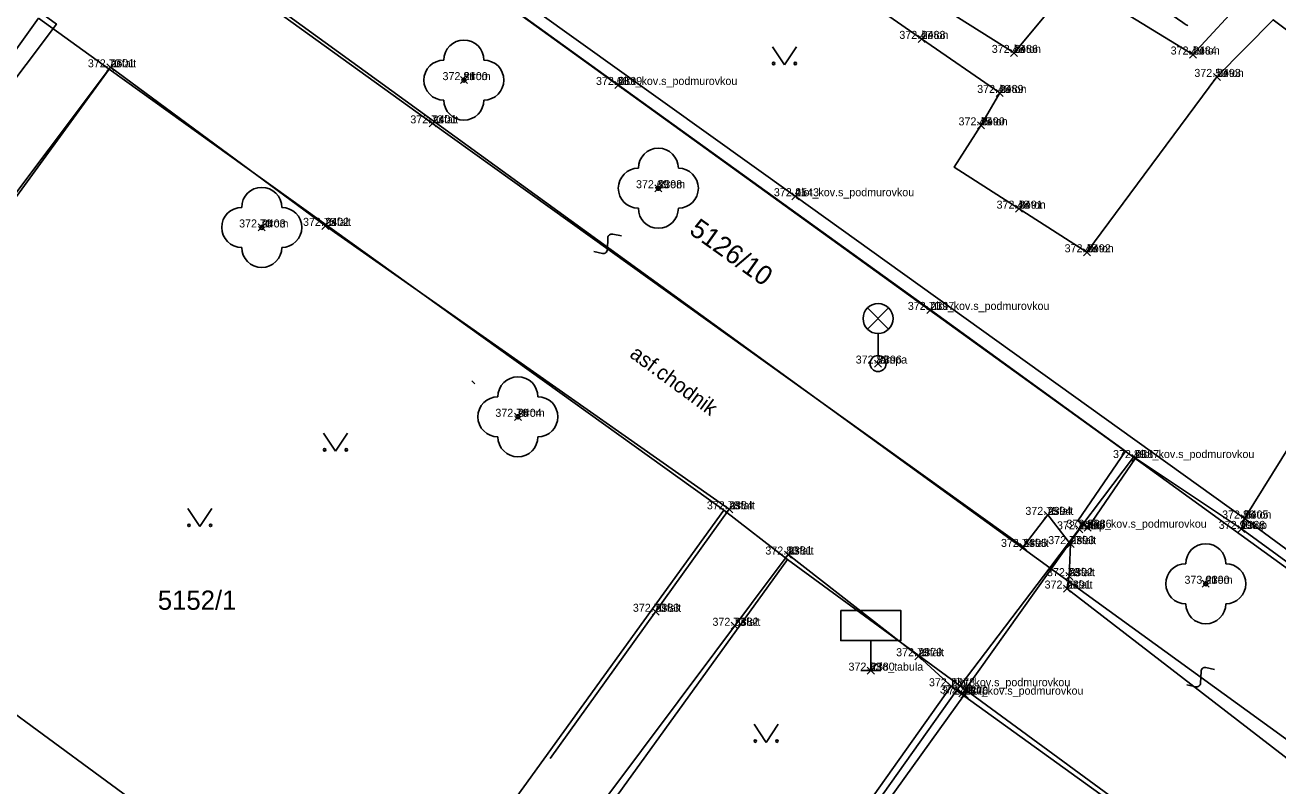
# Model space of a CAD drawing. Extents: x -400488 to -400124, y -1251493 to -1251223.
# Drawn here: x -400364.05 to -400332.74, y -1251372.84 to -1251353.83 of the extents above; entities that cross this region are included whole.
import ezdxf

# ---------------------------------------------------------------- set-up
doc = ezdxf.new("R2010")
doc.units = 0
for name, color, linetype in [('Level 20', 7, 'Continuous'), ('Level 21', 7, 'Continuous'), ('Level 22', 7, 'Continuous'), ('Level 23', 7, 'Continuous'), ('Level 31', 7, 'Continuous'), ('Level 32', 7, 'Continuous'), ('Level 35', 7, 'Continuous'), ('Level 36', 7, 'Continuous'), ('Level 49', 7, 'Continuous'), ('Level 53', 7, 'Continuous'), ('Level 63', 7, 'Continuous')]:
    doc.layers.add(name, color=color, linetype=linetype)

msp = doc.modelspace()

# ---------------------------------------------------------------- linework, layer by layer
at = {"layer": 'Level 20'}
for p, q in [((-400341.728, -1251354.268), (-400341.552, -1251354.092)), ((-400341.552, -1251354.268), (-400341.728, -1251354.092)), ((-400339.418, -1251354.618), (-400339.242, -1251354.442)), ((-400339.242, -1251354.618), (-400339.418, -1251354.442)), ((-400334.948, -1251354.658), (-400334.772, -1251354.482)), ((-400334.772, -1251354.658), (-400334.948, -1251354.482)), ((-400361.998, -1251354.978), (-400361.822, -1251354.802)), ((-400361.822, -1251354.978), (-400361.998, -1251354.802)), ((-400353.168, -1251355.298), (-400352.992, -1251355.122)), ((-400352.992, -1251355.298), (-400353.168, -1251355.122)), ((-400334.348, -1251355.218), (-400334.172, -1251355.042)), ((-400334.172, -1251355.218), (-400334.348, -1251355.042)), ((-400349.308, -1251355.418), (-400349.132, -1251355.242)), ((-400349.132, -1251355.418), (-400349.308, -1251355.242)), ((-400339.778, -1251355.618), (-400339.602, -1251355.442)), ((-400339.602, -1251355.618), (-400339.778, -1251355.442)), ((-400353.948, -1251356.378), (-400353.772, -1251356.202)), ((-400353.772, -1251356.378), (-400353.948, -1251356.202)), ((-400340.248, -1251356.428), (-400340.072, -1251356.252)), ((-400340.072, -1251356.428), (-400340.248, -1251356.252)), ((-400348.308, -1251357.998), (-400348.132, -1251357.822)), ((-400348.132, -1251357.998), (-400348.308, -1251357.822)), ((-400344.888, -1251358.198), (-400344.712, -1251358.022)), ((-400344.712, -1251358.198), (-400344.888, -1251358.022)), ((-400339.298, -1251358.508), (-400339.122, -1251358.332)), ((-400339.122, -1251358.508), (-400339.298, -1251358.332)), ((-400358.218, -1251358.978), (-400358.042, -1251358.802)), ((-400358.042, -1251358.978), (-400358.218, -1251358.802)), ((-400356.628, -1251358.938), (-400356.452, -1251358.762)), ((-400356.452, -1251358.938), (-400356.628, -1251358.762)), ((-400337.598, -1251359.598), (-400337.422, -1251359.422)), ((-400337.422, -1251359.598), (-400337.598, -1251359.422)), ((-400341.508, -1251361.038), (-400341.332, -1251360.862)), ((-400341.332, -1251361.038), (-400341.508, -1251360.862)), ((-400342.818, -1251362.378), (-400342.642, -1251362.202)), ((-400342.642, -1251362.378), (-400342.818, -1251362.202)), ((-400351.818, -1251363.708), (-400351.642, -1251363.532)), ((-400351.642, -1251363.708), (-400351.818, -1251363.532)), ((-400336.388, -1251364.738), (-400336.212, -1251364.562)), ((-400336.212, -1251364.738), (-400336.388, -1251364.562)), ((-400346.538, -1251366.018), (-400346.362, -1251365.842)), ((-400346.362, -1251366.018), (-400346.538, -1251365.842)), ((-400338.578, -1251366.158), (-400338.402, -1251365.982)), ((-400338.402, -1251366.158), (-400338.578, -1251365.982)), ((-400333.658, -1251366.248), (-400333.482, -1251366.072)), ((-400333.482, -1251366.248), (-400333.658, -1251366.072)), ((-400337.788, -1251366.518), (-400337.612, -1251366.342)), ((-400337.612, -1251366.518), (-400337.788, -1251366.342)), ((-400337.578, -1251366.478), (-400337.402, -1251366.302)), ((-400337.402, -1251366.478), (-400337.578, -1251366.302)), ((-400333.738, -1251366.508), (-400333.562, -1251366.332)), ((-400333.562, -1251366.508), (-400333.738, -1251366.332)), ((-400339.188, -1251366.958), (-400339.012, -1251366.782)), ((-400339.012, -1251366.958), (-400339.188, -1251366.782)), ((-400338.008, -1251366.888), (-400337.832, -1251366.712)), ((-400337.832, -1251366.888), (-400338.008, -1251366.712)), ((-400345.068, -1251367.148), (-400344.892, -1251366.972)), ((-400344.892, -1251367.148), (-400345.068, -1251366.972)), ((-400338.038, -1251367.688), (-400337.862, -1251367.512)), ((-400337.862, -1251367.688), (-400338.038, -1251367.512)), ((-400334.628, -1251367.878), (-400334.452, -1251367.702)), ((-400334.452, -1251367.878), (-400334.628, -1251367.702)), ((-400338.098, -1251367.998), (-400337.922, -1251367.822)), ((-400337.922, -1251367.998), (-400338.098, -1251367.822)), ((-400348.378, -1251368.578), (-400348.202, -1251368.402)), ((-400348.202, -1251368.578), (-400348.378, -1251368.402)), ((-400346.398, -1251368.928), (-400346.222, -1251368.752)), ((-400346.222, -1251368.928), (-400346.398, -1251368.752)), ((-400341.808, -1251369.688), (-400341.632, -1251369.512)), ((-400341.632, -1251369.688), (-400341.808, -1251369.512)), ((-400342.998, -1251370.048), (-400342.822, -1251369.872)), ((-400342.822, -1251370.048), (-400342.998, -1251369.872)), ((-400340.988, -1251370.438), (-400340.812, -1251370.262)), ((-400340.812, -1251370.438), (-400340.988, -1251370.262)), ((-400340.708, -1251370.618), (-400340.532, -1251370.442)), ((-400340.532, -1251370.618), (-400340.708, -1251370.442)), ((-400340.658, -1251370.648), (-400340.482, -1251370.472)), ((-400340.482, -1251370.648), (-400340.658, -1251370.472))]:
    msp.add_line(p, q, dxfattribs=at)
at = {"layer": 'Level 31'}
for points in [[(-400325.3, -1251345.13), (-400328.44, -1251348.18), (-400333.54, -1251353.13), (-400334.86, -1251354.57), (-400337.85, -1251352.74), (-400339.33, -1251354.53), (-400341.3, -1251353.29)], [(-400341.64, -1251354.18), (-400348.59, -1251349.35), (-400349.96, -1251351.43), (-400354.01, -1251348.56)], [(-400340.16, -1251356.34), (-400340.828, -1251357.382), (-400337.51, -1251359.51), (-400334.26, -1251355.13), (-400332.86, -1251353.7), (-400328.72, -1251356.82), (-400328.3, -1251357.14), (-400327.46, -1251357.74), (-400326.93, -1251358.11), (-400329.7, -1251364.82)], [(-400341.64, -1251354.18), (-400339.69, -1251355.53), (-400340.16, -1251356.34)], [(-400333.57, -1251366.16), (-400331.94, -1251363.54), (-400331.46, -1251363.76), (-400331.01, -1251364.01), (-400330.04, -1251364.51), (-400329.7, -1251364.82), (-400328.94, -1251365.47), (-400330.88, -1251368.13), (-400333.57, -1251366.16)]]:
    msp.add_lwpolyline(points, dxfattribs=at)
at = {"layer": 'Level 32'}
for p, q in [((-400342.91, -1251369.96), (-400342.91, -1251369.21)), ((-400343.16, -1251369.96), (-400342.66, -1251369.96))]:
    msp.add_line(p, q, dxfattribs=at)
for points in [[(-400385.43, -1251329.24), (-400385.81, -1251330.02), (-400386.13, -1251330.85), (-400386.185, -1251331.545), (-400386.09, -1251332.46), (-400385.712, -1251333.158), (-400385.21, -1251333.75), (-400379.16, -1251338.08), (-400353.86, -1251356.29)], [(-400365.68, -1251352.04), (-400363.26, -1251353.81), (-400367.84, -1251359.89)], [(-400361.91, -1251354.89), (-400366.49, -1251360.97)], [(-400350.926, -1251372.157), (-400346.45, -1251365.93), (-400356.54, -1251358.85), (-400361.91, -1251354.89)], [(-400332, -1251372.55), (-400338.01, -1251367.91), (-400337.95, -1251367.6), (-400337.92, -1251366.8), (-400338.49, -1251366.07), (-400339.1, -1251366.87), (-400353.86, -1251356.29)], [(-400340.9, -1251370.35), (-400341.72, -1251369.6), (-400344.98, -1251367.06), (-400349.554, -1251373.182)]]:
    msp.add_lwpolyline(points, dxfattribs=at)
msp.add_lwpolyline([(-400343.66, -1251368.46), (-400342.16, -1251368.46), (-400342.16, -1251369.21), (-400343.66, -1251369.21)], close=True, dxfattribs=at)
at = {"layer": 'Level 35'}
msp.add_line((-400345.145, -1251376.318), (-400340.9, -1251370.35), dxfattribs=at)
for points in [[(-400336.543, -1251364.474), (-400341.42, -1251360.95), (-400349.22, -1251355.33), (-400374.14, -1251337.36)], [(-400333.65, -1251366.42), (-400333.57, -1251366.16), (-400344.8, -1251358.11), (-400358.88, -1251348.03)], [(-400337.49, -1251366.39), (-400337.738, -1251366.221), (-400336.543, -1251364.474)], [(-400337.49, -1251366.39), (-400336.3, -1251364.65), (-400333.65, -1251366.42)], [(-400340.62, -1251370.53), (-400337.7, -1251366.43), (-400337.614, -1251366.305)], [(-400333.65, -1251366.42), (-400329.68, -1251369.31)], [(-400344.859, -1251376.524), (-400340.57, -1251370.56), (-400340.62, -1251370.53), (-400340.9, -1251370.35)]]:
    msp.add_lwpolyline(points, dxfattribs=at)
at = {"layer": 'Level 36'}
for p, q in [((-400345.07, -1251354.825), (-400345.37, -1251354.375)), ((-400345.07, -1251354.825), (-400344.77, -1251354.375)), ((-400356.289, -1251364.475), (-400356.589, -1251364.025)), ((-400356.289, -1251364.475), (-400355.989, -1251364.025)), ((-400345.527, -1251371.751), (-400345.827, -1251371.301)), ((-400345.527, -1251371.751), (-400345.227, -1251371.301))]:
    msp.add_line(p, q, dxfattribs=at)
for centre, radius in [((-400345.34, -1251354.795), 0.03), ((-400344.8, -1251354.795), 0.03), ((-400353.08, -1251355.21), 0.05), ((-400348.22, -1251357.91), 0.05), ((-400358.13, -1251358.89), 0.05), ((-400351.73, -1251363.62), 0.05), ((-400356.559, -1251364.445), 0.03), ((-400356.019, -1251364.445), 0.03), ((-400334.54, -1251367.79), 0.05), ((-400345.797, -1251371.721), 0.03), ((-400345.257, -1251371.721), 0.03)]:
    msp.add_circle(centre, radius, dxfattribs=at)
for centre, start, end in [((-400353.08, -1251354.71), 0, 180), ((-400353.58, -1251355.21), 90, 270), ((-400352.58, -1251355.21), 270, 90), ((-400353.08, -1251355.71), 180, 0), ((-400348.22, -1251357.41), 0, 180), ((-400348.72, -1251357.91), 90, 270), ((-400347.72, -1251357.91), 270, 90), ((-400358.13, -1251358.39), 0, 180), ((-400358.63, -1251358.89), 90, 270), ((-400357.63, -1251358.89), 270, 90), ((-400348.22, -1251358.41), 180, 0), ((-400358.13, -1251359.39), 180, 0), ((-400351.73, -1251363.12), 0, 180), ((-400352.23, -1251363.62), 90, 270), ((-400351.23, -1251363.62), 270, 90), ((-400351.73, -1251364.12), 180, 0), ((-400334.54, -1251367.29), 0, 180), ((-400335.04, -1251367.79), 90, 270), ((-400334.04, -1251367.79), 270, 90), ((-400334.54, -1251368.29), 180, 0)]:
    msp.add_arc(centre, 0.5, start, end, dxfattribs=at)
at = {"layer": 'Level 49'}
msp.add_line((-400352.802, -1251362.8), (-400352.878, -1251362.72), dxfattribs=at)
msp.add_spline([(-400334.986, -1251353.857), (-400335.08, -1251353.793), (-400335.621, -1251353.439), (-400336.177, -1251353.117), (-400336.753, -1251352.83), (-400336.828, -1251352.796), (-400337.672, -1251352.414), (-400337.958, -1251352.157), (-400338.343, -1251351.78), (-400338.709, -1251351.396), (-400339.424, -1251350.616), (-400340.592, -1251349.451), (-400340.813, -1251349.261), (-400341.045, -1251349.073), (-400341.469, -1251348.764), (-400341.908, -1251348.493), (-400342.354, -1251348.267), (-400342.583, -1251348.168), (-400342.819, -1251348.079), (-400343.277, -1251347.944), (-400343.745, -1251347.863), (-400344.204, -1251347.84), (-400344.431, -1251347.851), (-400344.655, -1251347.878), (-400345.127, -1251348.02), (-400345.595, -1251348.243), (-400345.973, -1251348.463), (-400346.327, -1251348.706), (-400346.625, -1251348.915)], degree=3, dxfattribs=at)
at = {"layer": 'Level 53'}
for p, q in [((-400342.995, -1251361.43), (-400342.465, -1251360.9)), ((-400342.465, -1251360.9), (-400342.995, -1251361.43)), ((-400342.465, -1251361.43), (-400342.995, -1251360.9)), ((-400342.73, -1251361.54), (-400342.73, -1251362.09))]:
    msp.add_line(p, q, dxfattribs=at)
for centre, radius in [((-400342.73, -1251361.165), 0.375), ((-400342.73, -1251362.29), 0.2)]:
    msp.add_circle(centre, radius, dxfattribs=at)
at = {"layer": 'Level 63'}
for p, q in [((-400381.14, -1251336.44), (-400338.44, -1251367.39)), ((-400336.35, -1251364.63), (-400362.18, -1251345.99)), ((-400362.18, -1251345.99), (-400336.35, -1251364.63)), ((-400363.71, -1251353.66), (-400374.2, -1251368.35)), ((-400361.94, -1251354.94), (-400363.71, -1251353.66)), ((-400363.71, -1251353.66), (-400361.94, -1251354.94)), ((-400372.54, -1251369.43), (-400361.94, -1251354.94)), ((-400346.58, -1251365.95), (-400361.94, -1251354.94)), ((-400361.94, -1251354.94), (-400346.58, -1251365.95)), ((-400382.94, -1251357.38), (-400335.26, -1251392.32)), ((-400349.494, -1251359.443), (-400349.483, -1251359.15)), ((-400349.361, -1251359.056), (-400349.144, -1251359.103)), ((-400349.833, -1251359.49), (-400349.615, -1251359.537)), ((-400336.35, -1251364.63), (-400338.44, -1251367.39)), ((-400338.44, -1251367.39), (-400336.35, -1251364.63)), ((-400298.43, -1251392.08), (-400336.35, -1251364.63)), ((-400336.35, -1251364.63), (-400298.43, -1251392.08)), ((-400359.98, -1251365.91), (-400359.68, -1251366.36)), ((-400359.68, -1251366.36), (-400359.38, -1251365.91)), ((-400346.58, -1251365.95), (-400357.17, -1251380.58)), ((-400344.99, -1251367.18), (-400346.58, -1251365.95)), ((-400346.58, -1251365.95), (-400344.99, -1251367.18)), ((-400344.99, -1251367.18), (-400356.64, -1251383.32)), ((-400340.68, -1251370.34), (-400344.99, -1251367.18)), ((-400344.99, -1251367.18), (-400340.68, -1251370.34)), ((-400338.44, -1251367.39), (-400340.68, -1251370.34)), ((-400340.68, -1251370.34), (-400338.44, -1251367.39)), ((-400338.44, -1251367.39), (-400330.89, -1251372.86)), ((-400334.538, -1251369.884), (-400334.32, -1251369.932)), ((-400334.671, -1251370.272), (-400334.659, -1251369.978)), ((-400340.77, -1251370.46), (-400347.59, -1251380.06)), ((-400347.59, -1251380.06), (-400340.77, -1251370.46)), ((-400340.68, -1251370.34), (-400340.77, -1251370.46)), ((-400340.77, -1251370.46), (-400340.68, -1251370.34)), ((-400333.11, -1251375.97), (-400340.77, -1251370.46)), ((-400340.77, -1251370.46), (-400333.11, -1251375.97)), ((-400333.07, -1251375.91), (-400340.68, -1251370.34)), ((-400335.01, -1251370.318), (-400334.792, -1251370.366))]:
    msp.add_line(p, q, dxfattribs=at)
for centre in [(-400359.95, -1251366.33), (-400359.41, -1251366.33)]:
    msp.add_circle(centre, 0.03, dxfattribs=at)
for centre, start, end in [((-400349.383, -1251359.154), 77.7527, 177.7631), ((-400349.594, -1251359.44), 257.753, 357.7631), ((-400334.559, -1251369.982), 77.7527, 177.7631), ((-400334.771, -1251370.268), 257.753, 357.7631)]:
    msp.add_arc(centre, 0.1, start, end, dxfattribs=at)

# ---------------------------------------------------------------- texts
at = {"layer": 'Level 21'}
for s, p in [('2488', (-400341.64, -1251354.18)), ('2486', (-400339.33, -1251354.53)), ('2484', (-400334.86, -1251354.57)), ('2601', (-400361.91, -1251354.89)), ('2400', (-400353.08, -1251355.21)), ('2399', (-400349.22, -1251355.33)), ('2493', (-400334.26, -1251355.13)), ('2489', (-400339.69, -1251355.53)), ('2401', (-400353.86, -1251356.29)), ('2490', (-400340.16, -1251356.34)), ('2398', (-400348.22, -1251357.91)), ('2543', (-400344.8, -1251358.11)), ('2491', (-400339.21, -1251358.42)), ('2402', (-400356.54, -1251358.85)), ('2403', (-400358.13, -1251358.89)), ('2492', (-400337.51, -1251359.51)), ('2397', (-400341.42, -1251360.95)), ('2396', (-400342.73, -1251362.29)), ('2404', (-400351.73, -1251363.62)), ('2387', (-400336.3, -1251364.65)), ('2384', (-400346.45, -1251365.93)), ('2394', (-400338.49, -1251366.07)), ('2405', (-400333.57, -1251366.16)), ('2385', (-400337.7, -1251366.43)), ('2386', (-400337.49, -1251366.39)), ('2388', (-400333.65, -1251366.42)), ('2395', (-400339.1, -1251366.87)), ('2393', (-400337.92, -1251366.8)), ('2381', (-400344.98, -1251367.06)), ('2392', (-400337.95, -1251367.6)), ('2391', (-400338.01, -1251367.91)), ('2390', (-400334.54, -1251367.79)), ('2383', (-400348.29, -1251368.49)), ('2382', (-400346.31, -1251368.84)), ('2379', (-400341.72, -1251369.6)), ('2380', (-400342.91, -1251369.96)), ('2378', (-400340.9, -1251370.35)), ('2377', (-400340.62, -1251370.53)), ('2376', (-400340.57, -1251370.56))]:
    msp.add_text(s, height=0.2, dxfattribs=at).set_placement(p)
at = {"layer": 'Level 22'}
for s, p in [('beton', (-400341.64, -1251354.18)), ('beton', (-400339.33, -1251354.53)), ('beton', (-400334.86, -1251354.57)), ('asfalt', (-400361.91, -1251354.89)), ('strom', (-400353.08, -1251355.21)), ('plot_kov.s_podmurovkou', (-400349.22, -1251355.33)), ('beton', (-400334.26, -1251355.13)), ('beton', (-400339.69, -1251355.53)), ('asfalt', (-400353.86, -1251356.29)), ('beton', (-400340.16, -1251356.34)), ('strom', (-400348.22, -1251357.91)), ('plot_kov.s_podmurovkou', (-400344.8, -1251358.11)), ('beton', (-400339.21, -1251358.42)), ('asfalt', (-400356.54, -1251358.85)), ('strom', (-400358.13, -1251358.89)), ('beton', (-400337.51, -1251359.51)), ('plot_kov.s_podmurovkou', (-400341.42, -1251360.95)), ('lampa', (-400342.73, -1251362.29)), ('strom', (-400351.73, -1251363.62)), ('plot_kov.s_podmurovkou', (-400336.3, -1251364.65)), ('asfalt', (-400346.45, -1251365.93)), ('asfalt', (-400338.49, -1251366.07)), ('beton', (-400333.57, -1251366.16)), ('vstup', (-400337.7, -1251366.43)), ('plot_kov.s_podmurovkou', (-400337.49, -1251366.39)), ('vstup', (-400333.65, -1251366.42)), ('asfalt', (-400339.1, -1251366.87)), ('asfalt', (-400337.92, -1251366.8)), ('asfalt', (-400344.98, -1251367.06)), ('asfalt', (-400337.95, -1251367.6)), ('asfalt', (-400338.01, -1251367.91)), ('strom', (-400334.54, -1251367.79)), ('asfalt', (-400348.29, -1251368.49)), ('asfalt', (-400346.31, -1251368.84)), ('asfalt', (-400341.72, -1251369.6)), ('info_tabula', (-400342.91, -1251369.96)), ('plot_kov.s_podmurovkou', (-400340.9, -1251370.35)), ('vstup', (-400340.62, -1251370.53)), ('plot_kov.s_podmurovkou', (-400340.57, -1251370.56))]:
    msp.add_text(s, height=0.2, dxfattribs=at).set_placement(p)
at = {"layer": 'Level 23'}
for s, p in [('372.47', (-400342.198, -1251354.18)), ('372.48', (-400339.888, -1251354.53)), ('372.49', (-400335.418, -1251354.57)), ('372.70', (-400362.476, -1251354.89)), ('372.81', (-400353.613, -1251355.21)), ('372.68', (-400349.778, -1251355.33)), ('372.50', (-400334.826, -1251355.13)), ('372.46', (-400340.253, -1251355.53)), ('372.73', (-400354.418, -1251356.29)), ('372.45', (-400340.719, -1251356.34)), ('372.69', (-400348.778, -1251357.91)), ('372.41', (-400345.333, -1251358.11)), ('372.48', (-400339.768, -1251358.42)), ('372.75', (-400357.099, -1251358.85)), ('372.70', (-400358.696, -1251358.89)), ('372.48', (-400338.068, -1251359.51)), ('372.70', (-400341.986, -1251360.95)), ('372.82', (-400343.288, -1251362.29)), ('372.76', (-400352.293, -1251363.62)), ('372.89', (-400336.858, -1251364.65)), ('372.78', (-400347.008, -1251365.93)), ('372.75', (-400339.049, -1251366.07)), ('372.86', (-400334.133, -1251366.16)), ('372.79', (-400338.258, -1251366.43)), ('372.81', (-400338.023, -1251366.39)), ('372.90', (-400334.216, -1251366.42)), ('372.74', (-400339.658, -1251366.87)), ('372.77', (-400338.478, -1251366.8)), ('372.80', (-400345.546, -1251367.06)), ('372.78', (-400338.508, -1251367.6)), ('372.77', (-400338.568, -1251367.91)), ('373.01', (-400335.073, -1251367.79)), ('372.70', (-400348.856, -1251368.49)), ('372.73', (-400346.868, -1251368.84)), ('372.79', (-400342.278, -1251369.6)), ('372.83', (-400343.468, -1251369.96)), ('372.77', (-400341.458, -1251370.35)), ('372.80', (-400341.186, -1251370.53)), ('372.76', (-400341.133, -1251370.56))]:
    msp.add_text(s, height=0.2, dxfattribs=at).set_placement(p)
at = {"layer": 'Level 32'}
msp.add_text('asf.chodnik', height=0.375, rotation=323.6458, dxfattribs=at).set_placement((-400348.962, -1251362.11))
at = {"layer": 'Level 63'}
msp.add_text('5126/10', height=0.48, rotation=324.4579, dxfattribs=at).set_placement((-400347.475, -1251359.025))
msp.add_text('5152/1', height=0.48, dxfattribs=at).set_placement((-400360.727, -1251368.44))

doc.saveas('drawing.dxf')
